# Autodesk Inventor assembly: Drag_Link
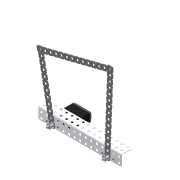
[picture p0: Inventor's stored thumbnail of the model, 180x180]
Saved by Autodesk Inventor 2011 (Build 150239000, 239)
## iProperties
Created: 2008-04
Part Number: Drag_Link
Document SubType Name: Assembly
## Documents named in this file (9)
- C:\Data Folder\VEX 2011\Inventor Datasets\Unit 15\Drag_Link.iam
- C:\Data Folder\VEX 2011\Inventor Datasets\Unit 15\Components\ANG-HH22-15-SK RevA.ipt
- C:\Data Folder\VEX 2011\Inventor Datasets\Unit 15\Components\BEARING-FLAT.ipt
- C:\Data Folder\VEX 2011\Inventor Datasets\Unit 15\Components\VEX_Motor_Animate.iam
- C:\Data Folder\VEX 2011\Inventor Datasets\Unit 15\Components\VL-BAR-15.ipt
- C:\Data Folder\VEX 2011\Inventor Datasets\Unit 15\Components\VL-BAR-12.ipt
- C:\Data Folder\VEX 2011\Inventor Datasets\Unit 15\Components\VL-BAR-14.ipt
- C:\Data Folder\VEX 2011\Inventor Datasets\Unit 15\Components\SHAFT-1000.ipt
- C:\Data Folder\VEX 2011\Inventor Datasets\Unit 15\Components\Shaft_Collar.iam
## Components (11 placed, 8 different names)
1. ANG-HH22-15-SK RevA:1 — Mate:1, Mate:2, Mate:3, Mate:4, Mate:5, Mate:6, Mate:11
2. BEARING-FLAT:1 — Mate:1, Mate:5, Mate:6, Mate:7, Mate:8, Mate:9, Mate:18
3. BEARING-FLAT:2 — Mate:2, Mate:3, Mate:4, Mate:19
4. VEX_Motor_Animate:1 [sub-assembly] — Mate:7, Mate:8, Mate:9, Mate:20
5. VL-BAR-12:1 — Mate:11, Mate:12, Mate:13, Mate:17, Mate:18, Angle:2, Mate:23
6. VL-BAR-15:1 — Mate:15, Mate:16, Mate:19, Mate:21, Angle:1, Mate:25
7. VL-BAR-14:1 — Mate:12, Mate:13, Mate:15, Mate:16
8. SHAFT-1000:1 — Mate:17, Mate:20, Flush:1, Angle:2, Mate:22, Angle:3
9. SHAFT-1000:2 — Mate:21, Flush:1, Angle:1, Mate:24, Angle:4
10. Shaft_Collar:1 [sub-assembly] — Mate:22, Mate:23, Angle:3
11. Shaft_Collar:2 [sub-assembly] — Mate:24, Mate:25, Angle:4
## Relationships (28: Mate 23, Angle 4, Flush 1)
- Mate:1: ANG-HH22-15-SK RevA:1 ↔ BEARING-FLAT:1
- Mate:2: ANG-HH22-15-SK RevA:1 ↔ BEARING-FLAT:2
- Mate:3: ANG-HH22-15-SK RevA:1 ↔ BEARING-FLAT:2
- Mate:4: ANG-HH22-15-SK RevA:1 ↔ BEARING-FLAT:2
- Mate:5: ANG-HH22-15-SK RevA:1 ↔ BEARING-FLAT:1
- Mate:6: ANG-HH22-15-SK RevA:1 ↔ BEARING-FLAT:1
- Mate:7: BEARING-FLAT:1 ↔ VEX_Motor_Animate:1
- Mate:8: BEARING-FLAT:1 ↔ VEX_Motor_Animate:1
- Mate:9: BEARING-FLAT:1 ↔ VEX_Motor_Animate:1
- Mate:11: ANG-HH22-15-SK RevA:1 ↔ VL-BAR-12:1
- Mate:12: VL-BAR-12:1 ↔ VL-BAR-14:1
- Mate:13: VL-BAR-12:1 ↔ VL-BAR-14:1
- Mate:15: VL-BAR-15:1 ↔ VL-BAR-14:1
- Mate:16: VL-BAR-15:1 ↔ VL-BAR-14:1
- Mate:17: VL-BAR-12:1 ↔ SHAFT-1000:1
- Mate:18: BEARING-FLAT:1 ↔ VL-BAR-12:1
- Mate:19: BEARING-FLAT:2 ↔ VL-BAR-15:1
- Mate:20: VEX_Motor_Animate:1 ↔ SHAFT-1000:1
- Mate:21: VL-BAR-15:1 ↔ SHAFT-1000:2
- Flush:1: SHAFT-1000:1 ↔ SHAFT-1000:2
- Angle:1: VL-BAR-15:1 ↔ SHAFT-1000:2
- Angle:2: VL-BAR-12:1 ↔ SHAFT-1000:1
- Mate:22: SHAFT-1000:1 ↔ Shaft_Collar:1
- Mate:23: VL-BAR-12:1 ↔ Shaft_Collar:1
- Angle:3: SHAFT-1000:1 ↔ Shaft_Collar:1
- Mate:24: SHAFT-1000:2 ↔ Shaft_Collar:2
- Mate:25: VL-BAR-15:1 ↔ Shaft_Collar:2
- Angle:4: SHAFT-1000:2 ↔ Shaft_Collar:2
## Named parameters: Simulation_Timeline = 0
